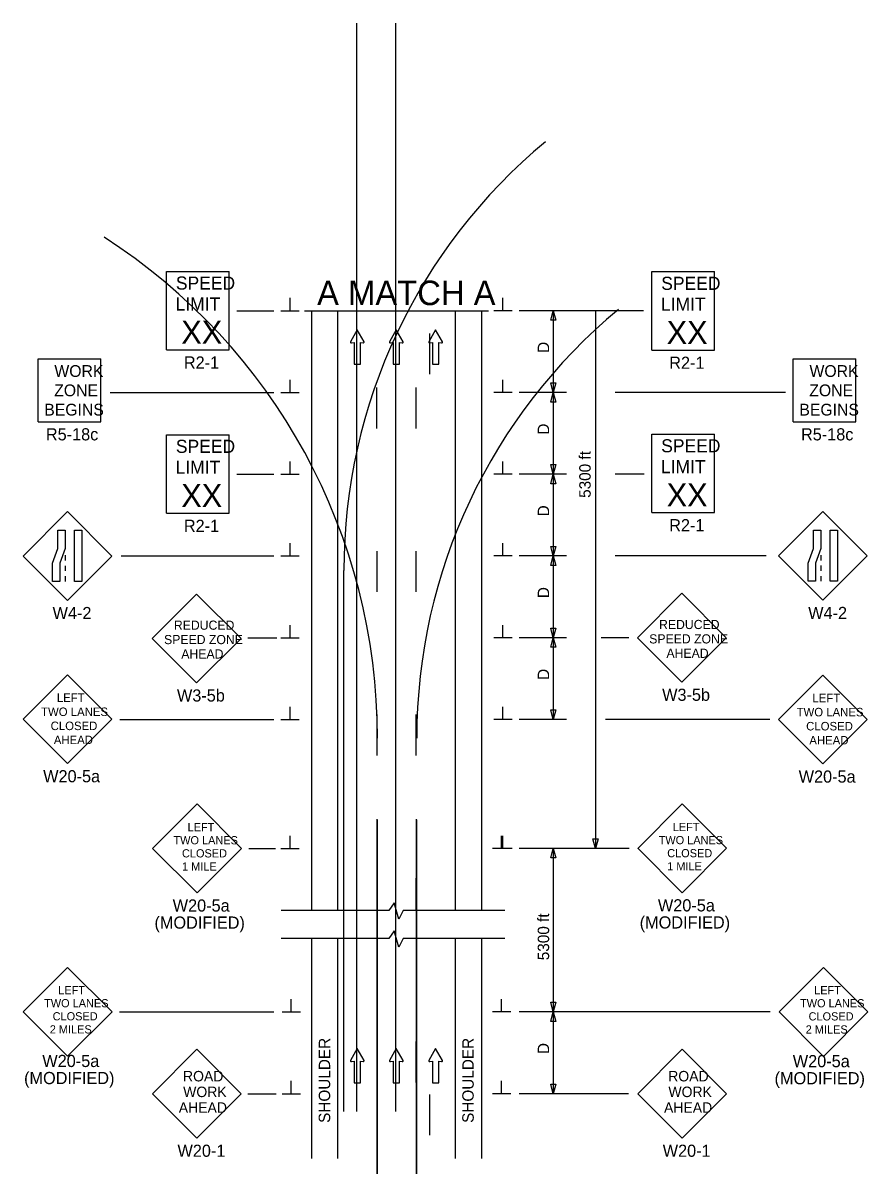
# Model space of a CAD drawing. Extents: x 16728 to 19508, y 5553 to 7079.
# Drawn here: x 17850 to 18368, y 6375 to 7079 of the extents above; entities that cross this region are included whole.
import ezdxf

# ---------------------------------------------------------------- set-up
doc = ezdxf.new("R2010")
doc.units = 0
for name, color, linetype in [('ALI_LEGAL_EX', 7, 'Continuous'), ('MT_SCRATCH_LEVEL_E', 7, 'Continuous'), ('PAVT_EDGE_EX', 7, 'Continuous'), ('TRAFFIC_SIGNS_PR', 7, 'Continuous'), ('TYPICAL_TEXT_DIMEN_PR', 7, 'Continuous')]:
    doc.layers.add(name, color=color, linetype=linetype)

msp = doc.modelspace()

# ---------------------------------------------------------------- linework, layer by layer
at = {"layer": 'ALI_LEGAL_EX'}
for p, q in [((18054.48, 7078.99), (18054.48, 6413.36)), ((18078.48, 7078.99), (18078.48, 6413.36)), ((18054.48, 6981.91), (18054.48, 6413.36)), ((18078.48, 6981.91), (18078.48, 6413.36)), ((18046.81, 6413.36), (18046.81, 6744.25)), ((18067.05, 6592.15), (18067.05, 6515)), ((18067.45, 6375.08), (18067.45, 6591.74)), ((18091.05, 6592.15), (18091.05, 6515)), ((18091.45, 6375.08), (18091.45, 6591.74)), ((18067.05, 6569), (18067.05, 6375.08)), ((18091.05, 6569), (18091.05, 6375.08))]:
    msp.add_line(p, q, dxfattribs=at)
for points in [[(18099.19, 6889.18), (18099.19, 6864.18)], [(18067.05, 6831.03), (18067.05, 6856.03)], [(18091.05, 6831.03), (18091.05, 6856.03)], [(18067.05, 6756.03), (18067.05, 6731.03)], [(18067.05, 6756.03), (18067.05, 6731.03)], [(18091.05, 6731.03), (18091.05, 6756.03)], [(18067.05, 6656.03), (18067.05, 6631.03)], [(18067.05, 6656.03), (18067.05, 6631.03)], [(18091.05, 6631.03), (18091.05, 6656.03)], [(18067.05, 6556.03), (18067.05, 6531.03)], [(18067.05, 6556.03), (18067.05, 6536.14)], [(18091.05, 6536.14), (18091.05, 6556.03)], [(18067.05, 6456.03), (18067.05, 6431.03)], [(18067.05, 6456.03), (18067.05, 6431.03)], [(18091.05, 6431.03), (18091.05, 6456.03)], [(18099.19, 6423.79), (18099.19, 6398.79)]]:
    msp.add_lwpolyline(points, dxfattribs=at)
for centre, radius, start, end in [((18386.81, 6744.25), 340, 129.56655, 180), ((17703.45, 6641.72), 364, 0, 57.29578), ((18431.45, 6641.72), 340, 129.56655, 180)]:
    msp.add_arc(centre, radius, start, end, dxfattribs=at)
at = {"layer": 'MT_SCRATCH_LEVEL_E'}
for p, q in [((18055.05, 6891.26), (18050.94, 6884.02)), ((18059.19, 6884.02), (18055.05, 6891.26)), ((18078.95, 6891.26), (18074.84, 6884.02)), ((18083.1, 6884.02), (18078.95, 6891.26)), ((18103, 6891.26), (18098.89, 6884.02)), ((18107.15, 6884.02), (18103, 6891.26)), ((18051.42, 6883.34), (18053.19, 6883.65)), ((18053.19, 6883.65), (18053.19, 6870.4)), ((18056.94, 6870.4), (18056.94, 6883.65)), ((18056.94, 6883.65), (18058.71, 6883.34)), ((18075.32, 6883.34), (18077.1, 6883.65)), ((18077.1, 6883.65), (18077.1, 6870.4)), ((18080.84, 6870.4), (18080.84, 6883.65)), ((18080.84, 6883.65), (18082.62, 6883.34)), ((18099.37, 6883.34), (18101.15, 6883.65)), ((18101.15, 6883.65), (18101.15, 6870.4)), ((18104.89, 6870.4), (18104.89, 6883.65)), ((18104.89, 6883.65), (18106.67, 6883.34)), ((18053.19, 6870.4), (18056.94, 6870.4)), ((18077.1, 6870.4), (18080.84, 6870.4)), ((18101.15, 6870.4), (18104.89, 6870.4)), ((18055.05, 6451.78), (18050.94, 6444.54)), ((18059.19, 6444.54), (18055.05, 6451.78)), ((18078.95, 6451.78), (18074.84, 6444.54)), ((18083.1, 6444.54), (18078.95, 6451.78)), ((18103, 6451.78), (18098.89, 6444.54)), ((18107.15, 6444.54), (18103, 6451.78)), ((18051.42, 6443.86), (18053.19, 6444.17)), ((18053.19, 6444.17), (18053.19, 6430.92)), ((18056.94, 6430.92), (18056.94, 6444.17)), ((18056.94, 6444.17), (18058.71, 6443.86)), ((18075.32, 6443.86), (18077.1, 6444.17)), ((18077.1, 6444.17), (18077.1, 6430.92)), ((18080.84, 6430.92), (18080.84, 6444.17)), ((18080.84, 6444.17), (18082.62, 6443.86)), ((18099.37, 6443.86), (18101.15, 6444.17)), ((18101.15, 6444.17), (18101.15, 6430.92)), ((18104.89, 6430.92), (18104.89, 6444.17)), ((18104.89, 6444.17), (18106.67, 6443.86)), ((18053.19, 6430.92), (18056.94, 6430.92)), ((18077.1, 6430.92), (18080.84, 6430.92)), ((18101.15, 6430.92), (18104.89, 6430.92))]:
    msp.add_line(p, q, dxfattribs=at)
for centre, start, end in [((18051.34, 6883.8), 150.42484, 279.96381), ((18058.78, 6883.8), 260.03619, 29.77312), ((18075.25, 6883.8), 150.42484, 279.96381), ((18082.69, 6883.8), 260.03619, 29.77312), ((18099.3, 6883.8), 150.42484, 279.96381), ((18106.74, 6883.8), 260.03619, 29.77312), ((18051.34, 6444.32), 150.42484, 279.96381), ((18058.78, 6444.32), 260.03619, 29.77312), ((18075.25, 6444.32), 150.42484, 279.96381), ((18082.69, 6444.32), 260.03619, 29.77312), ((18099.3, 6444.32), 150.42484, 279.96381), ((18106.74, 6444.32), 260.03619, 29.77312)]:
    msp.add_arc(centre, 0.463, start, end, dxfattribs=at)
at = {"layer": 'PAVT_EDGE_EX'}
for p, q in [((18027.05, 6903.04), (18027.05, 6536.14)), ((18043.05, 6903.04), (18043.05, 6536.14)), ((18115.05, 6903.04), (18115.05, 6536.14)), ((18131.05, 6903.04), (18131.05, 6536.14)), ((18027.05, 6519), (18027.05, 6384.62)), ((18043.05, 6519), (18043.05, 6384.62)), ((18115.05, 6519), (18115.05, 6384.62)), ((18131.05, 6519), (18131.05, 6384.62))]:
    msp.add_line(p, q, dxfattribs=at)
at = {"layer": 'TRAFFIC_SIGNS_PR'}
for p, q in [((17938.24, 6927.1), (17976.64, 6927.1)), ((17938.24, 6879.1), (17938.24, 6927.1)), ((17976.64, 6879.1), (17976.64, 6927.1)), ((18235.32, 6926.94), (18273.72, 6926.94)), ((18235.32, 6878.94), (18235.32, 6926.94)), ((18273.72, 6878.94), (18273.72, 6926.94)), ((17938.24, 6879.1), (17976.64, 6879.1)), ((18235.32, 6878.94), (18273.72, 6878.94)), ((17859.66, 6835.18), (17859.66, 6873.58)), ((17859.66, 6873.58), (17898.06, 6873.58)), ((17898.06, 6835.18), (17898.06, 6873.58)), ((18321.83, 6835.18), (18321.83, 6873.58)), ((18321.83, 6873.58), (18360.23, 6873.58)), ((18360.23, 6835.18), (18360.23, 6873.58)), ((17859.66, 6835.18), (17898.06, 6835.18)), ((18321.83, 6835.18), (18360.23, 6835.18)), ((17938.24, 6827.23), (17976.64, 6827.23)), ((17938.24, 6779.23), (17938.24, 6827.23)), ((17976.64, 6779.23), (17976.64, 6827.23)), ((18235.3, 6827.58), (18273.7, 6827.58)), ((18235.3, 6779.58), (18235.3, 6827.58)), ((18273.7, 6779.58), (18273.7, 6827.58)), ((17877.61, 6780.17), (17850.46, 6753.01)), ((17904.76, 6753.01), (17877.61, 6780.17)), ((17938.24, 6779.23), (17976.64, 6779.23)), ((18235.3, 6779.58), (18273.7, 6779.58)), ((18340.09, 6780.22), (18312.93, 6753.07)), ((18367.24, 6753.07), (18340.09, 6780.22)), ((17850.46, 6753.01), (17877.61, 6725.86)), ((17876.36, 6753.51), (17876.36, 6750.31)), ((17877.61, 6725.86), (17904.76, 6753.01)), ((18312.93, 6753.07), (18340.09, 6725.92)), ((18338.84, 6753.56), (18338.84, 6750.36)), ((18340.09, 6725.92), (18367.24, 6753.07)), ((17876.36, 6747.11), (17876.36, 6743.91)), ((18338.84, 6747.16), (18338.84, 6743.96)), ((17876.36, 6740.71), (17876.36, 6737.51)), ((18338.84, 6740.76), (18338.84, 6737.56)), ((17956.74, 6729.78), (17929.59, 6702.62)), ((17983.89, 6702.62), (17956.74, 6729.78)), ((18253.69, 6730.2), (18226.54, 6703.05)), ((18280.85, 6703.05), (18253.69, 6730.2)), ((17929.59, 6702.62), (17956.74, 6675.47)), ((17956.74, 6675.47), (17983.89, 6702.62)), ((18226.54, 6703.05), (18253.69, 6675.89)), ((18253.69, 6675.89), (18280.85, 6703.05)), ((17877.67, 6680.36), (17850.51, 6653.21)), ((17904.82, 6653.21), (17877.67, 6680.36)), ((18340.09, 6680.16), (18312.93, 6653)), ((18367.24, 6653), (18340.09, 6680.16)), ((17850.51, 6653.21), (17877.67, 6626.06)), ((17877.67, 6626.06), (17904.82, 6653.21)), ((18312.93, 6653), (18340.09, 6625.85)), ((18340.09, 6625.85), (18367.24, 6653)), ((17956.96, 6601.39), (17929.77, 6574.2)), ((17984.15, 6574.2), (17956.96, 6601.39)), ((18253.94, 6601.39), (18226.75, 6574.21)), ((18281.12, 6574.3), (18253.94, 6601.49)), ((17929.77, 6574.2), (17956.96, 6547.01)), ((17956.96, 6547.01), (17984.15, 6574.2)), ((18226.75, 6574.3), (18253.94, 6547.11)), ((18253.94, 6547.11), (18281.12, 6574.3)), ((17877.78, 6501.43), (17850.59, 6474.24)), ((17904.96, 6474.24), (17877.78, 6501.43)), ((18340.47, 6501.39), (18313.28, 6474.2)), ((18367.65, 6474.2), (18340.47, 6501.39)), ((17850.59, 6474.24), (17877.78, 6447.06)), ((17877.78, 6447.06), (17904.96, 6474.24)), ((18313.28, 6474.2), (18340.47, 6447.01)), ((18340.47, 6447.01), (18367.65, 6474.2)), ((17956.84, 6451.32), (17929.69, 6424.16)), ((17983.99, 6424.16), (17956.84, 6451.32)), ((18253.84, 6451.32), (18226.69, 6424.16)), ((18280.99, 6424.16), (18253.84, 6451.32)), ((17929.69, 6424.16), (17956.84, 6397.01)), ((17956.84, 6397.01), (17983.99, 6424.16)), ((18226.69, 6424.16), (18253.84, 6397.01)), ((18253.84, 6397.01), (18280.99, 6424.16))]:
    msp.add_line(p, q, dxfattribs=at)
for points in [[(17876.36, 6768.75), (17876.36, 6757.57), (17873.02, 6748.69), (17873.02, 6737.51), (17868.52, 6737.51), (17868.52, 6748.69), (17871.87, 6757.57), (17871.87, 6768.75)], [(17886.5, 6768.75), (17886.5, 6737.51), (17882, 6737.51), (17882, 6768.75)], [(18338.84, 6768.8), (18338.84, 6757.62), (18335.5, 6748.74), (18335.5, 6737.56), (18331, 6737.56), (18331, 6748.74), (18334.35, 6757.62), (18334.35, 6768.8)], [(18348.98, 6768.8), (18348.98, 6737.56), (18344.48, 6737.56), (18344.48, 6768.8)]]:
    msp.add_lwpolyline(points, close=True, dxfattribs=at)
at = {"layer": 'TYPICAL_TEXT_DIMEN_PR'}
for p, q in [((18013.92, 6903.04), (18013.92, 6910.83)), ((18144.17, 6903.04), (18144.17, 6910.83)), ((17981.38, 6903.04), (18004.05, 6903.04)), ((18008.3, 6903.04), (18019.55, 6903.04)), ((18022.72, 6903.04), (18135.37, 6903.04)), ((18149.8, 6903.04), (18138.55, 6903.04)), ((18230.27, 6903.04), (18154.05, 6903.04)), ((18173.48, 6897.18), (18175.05, 6903.04)), ((18175.05, 6903.04), (18175.05, 6853.04)), ((18175.05, 6903.04), (18176.62, 6897.18)), ((18200.89, 6903.04), (18200.89, 6574.2)), ((18175.05, 6897.18), (18173.48, 6897.18)), ((18176.62, 6897.18), (18175.05, 6897.18)), ((18013.92, 6853.04), (18013.92, 6860.83)), ((18144.17, 6853.04), (18144.17, 6860.83)), ((18175.05, 6853.04), (18173.48, 6858.91)), ((18173.48, 6858.91), (18175.05, 6858.91)), ((18175.05, 6858.91), (18176.62, 6858.91)), ((18176.62, 6858.91), (18175.05, 6853.04)), ((17903.73, 6853.04), (18004.05, 6853.04)), ((18008.3, 6853.04), (18019.55, 6853.04)), ((18149.8, 6853.04), (18138.55, 6853.04)), ((18183.05, 6853.04), (18154.05, 6853.04)), ((18173.48, 6847.18), (18175.05, 6853.04)), ((18175.05, 6853.04), (18175.05, 6803.04)), ((18175.05, 6853.04), (18176.62, 6847.18)), ((18317.09, 6853.04), (18212.91, 6853.04)), ((18175.05, 6847.18), (18173.48, 6847.18)), ((18176.62, 6847.18), (18175.05, 6847.18)), ((18013.92, 6803.04), (18013.92, 6810.83)), ((18144.17, 6803.04), (18144.17, 6810.83)), ((18175.05, 6803.04), (18173.48, 6808.91)), ((18173.48, 6808.91), (18175.05, 6808.91)), ((18175.05, 6808.91), (18176.62, 6808.91)), ((18176.62, 6808.91), (18175.05, 6803.04)), ((17981.38, 6803.04), (18004.05, 6803.04)), ((18008.3, 6803.04), (18019.55, 6803.04)), ((18149.8, 6803.04), (18138.55, 6803.04)), ((18183.05, 6803.04), (18154.05, 6803.04)), ((18173.48, 6797.18), (18175.05, 6803.04)), ((18175.05, 6803.04), (18175.05, 6753.04)), ((18175.05, 6803.04), (18176.62, 6797.18)), ((18230.75, 6803.04), (18212.91, 6803.04)), ((18175.05, 6797.18), (18173.48, 6797.18)), ((18176.62, 6797.18), (18175.05, 6797.18)), ((18013.92, 6753.04), (18013.92, 6760.83)), ((18144.17, 6753.04), (18144.17, 6760.83)), ((18175.05, 6753.04), (18173.48, 6758.91)), ((18173.48, 6758.91), (18175.05, 6758.91)), ((18175.05, 6758.91), (18176.62, 6758.91)), ((18176.62, 6758.91), (18175.05, 6753.04)), ((17910.58, 6753.04), (18004.05, 6753.04)), ((18008.3, 6753.04), (18019.55, 6753.04)), ((18149.8, 6753.04), (18138.55, 6753.04)), ((18183.05, 6753.04), (18154.05, 6753.04)), ((18173.48, 6747.18), (18175.05, 6753.04)), ((18175.05, 6753.04), (18175.05, 6703.04)), ((18175.05, 6753.04), (18176.62, 6747.18)), ((18305.38, 6753.04), (18212.91, 6753.04)), ((18175.05, 6747.18), (18173.48, 6747.18)), ((18176.62, 6747.18), (18175.05, 6747.18)), ((18013.92, 6703.04), (18013.92, 6710.83)), ((18144.17, 6703.04), (18144.17, 6710.83)), ((18175.05, 6703.04), (18173.48, 6708.91)), ((18173.48, 6708.91), (18175.05, 6708.91)), ((18175.05, 6708.91), (18176.62, 6708.91)), ((18176.62, 6708.91), (18175.05, 6703.04)), ((17988.12, 6703.04), (18005.83, 6703.04)), ((18008.3, 6703.04), (18019.55, 6703.04)), ((18149.8, 6703.04), (18138.55, 6703.04)), ((18183.05, 6703.04), (18154.05, 6703.04)), ((18173.48, 6697.18), (18175.05, 6703.04)), ((18175.05, 6703.04), (18175.05, 6653.04)), ((18175.05, 6703.04), (18176.62, 6697.18)), ((18221.32, 6703.04), (18204.38, 6703.04)), ((18175.05, 6697.18), (18173.48, 6697.18)), ((18176.62, 6697.18), (18175.05, 6697.18)), ((18013.92, 6653.04), (18013.92, 6660.83)), ((18144.17, 6653.04), (18144.17, 6660.83)), ((17909.79, 6653.04), (18004.05, 6653.04)), ((18008.3, 6653.04), (18019.55, 6653.04)), ((18149.8, 6653.04), (18138.55, 6653.04)), ((18183.05, 6653.04), (18154.05, 6653.04)), ((18175.05, 6653.04), (18173.48, 6658.91)), ((18173.48, 6658.91), (18175.05, 6658.91)), ((18175.05, 6658.91), (18176.62, 6658.91)), ((18176.62, 6658.91), (18175.05, 6653.04)), ((18307.54, 6653.04), (18206.97, 6653.04)), ((18013.92, 6574.2), (18013.92, 6581.98)), ((18143.42, 6574.2), (18143.42, 6581.98)), ((18144.17, 6574.2), (18144.17, 6581.98)), ((18200.89, 6574.2), (18199.32, 6580.06)), ((18199.32, 6580.06), (18200.89, 6580.06)), ((18200.89, 6580.06), (18202.46, 6580.06)), ((18202.46, 6580.06), (18200.89, 6574.2)), ((17988.75, 6574.2), (18005.04, 6574.2)), ((18008.3, 6574.2), (18019.55, 6574.2)), ((18149.05, 6574.2), (18137.8, 6574.2)), ((18149.8, 6574.2), (18138.55, 6574.2)), ((18221.46, 6574.2), (18154.05, 6574.2)), ((18173.48, 6568.34), (18175.05, 6574.2)), ((18175.05, 6568.34), (18173.48, 6568.34)), ((18175.05, 6574.2), (18175.05, 6474.2)), ((18175.05, 6574.2), (18176.62, 6568.34)), ((18176.62, 6568.34), (18175.05, 6568.34)), ((18077.65, 6540.94), (18074.4, 6536.14)), ((18080.39, 6531), (18077.65, 6540.94)), ((18074.4, 6536.14), (18008.45, 6536.14)), ((18083.14, 6536.14), (18080.39, 6531)), ((18145.47, 6536.14), (18083.14, 6536.14)), ((18074.4, 6519), (18008.45, 6519)), ((18077.65, 6523.8), (18074.4, 6519)), ((18080.39, 6513.86), (18077.65, 6523.8)), ((18083.14, 6519), (18080.39, 6513.86)), ((18145.47, 6519), (18083.14, 6519)), ((18014.67, 6474.2), (18014.67, 6481.98)), ((18143.42, 6474.2), (18143.42, 6481.98)), ((18175.05, 6474.2), (18173.48, 6480.06)), ((18173.48, 6480.06), (18175.05, 6480.06)), ((18175.05, 6480.06), (18176.62, 6480.06)), ((18176.62, 6480.06), (18175.05, 6474.2)), ((17909.49, 6474.2), (18004.05, 6474.2)), ((18009.05, 6474.2), (18020.3, 6474.2)), ((18149.05, 6474.2), (18137.8, 6474.2)), ((18307.79, 6474.2), (18154.05, 6474.2)), ((18173.48, 6468.34), (18175.05, 6474.2)), ((18175.05, 6474.2), (18175.05, 6424.2)), ((18175.05, 6474.2), (18176.62, 6468.34)), ((18175.05, 6468.34), (18173.48, 6468.34)), ((18176.62, 6468.34), (18175.05, 6468.34)), ((18014.67, 6424.2), (18014.67, 6431.98)), ((18143.42, 6424.2), (18143.42, 6431.98)), ((18175.05, 6424.2), (18173.48, 6430.06)), ((18173.48, 6430.06), (18175.05, 6430.06)), ((18175.05, 6430.06), (18176.62, 6430.06)), ((18176.62, 6430.06), (18175.05, 6424.2)), ((17988, 6424.2), (18005.31, 6424.2)), ((18009.05, 6424.2), (18020.3, 6424.2)), ((18149.05, 6424.2), (18137.8, 6424.2)), ((18221.16, 6424.2), (18154.05, 6424.2))]:
    msp.add_line(p, q, dxfattribs=at)

# ---------------------------------------------------------------- texts
at = {"layer": 'TRAFFIC_SIGNS_PR'}
for s, height, p in [('SPEED', 8, (17944.01, 6915.96)), ('SPEED', 8, (18241.09, 6915.8)), ('LIMIT', 8, (17943.84, 6903.16)), ('LIMIT', 8, (18240.93, 6903)), ('XX', 14.031, (17947.35, 6882.86)), ('XX', 14.031, (18244.43, 6882.7)), ('R2-1', 7.44, (17948.92, 6867.66)), ('R2-1', 7.44, (18246, 6867.5)), ('WORK', 7.217, (17869.66, 6862.54)), ('WORK', 7.217, (18331.84, 6862.54)), ('ZONE', 7.217, (17869.54, 6850.73)), ('ZONE', 7.217, (18331.72, 6850.73)), ('BEGINS', 7.217, (17863.47, 6838.93)), ('BEGINS', 7.217, (18325.65, 6838.93)), ('R5-18c', 7.44, (17864.47, 6823.74)), ('R5-18c', 7.44, (18326.65, 6823.74)), ('SPEED', 8, (17944.01, 6816.1)), ('SPEED', 8, (18241.07, 6816.44)), ('LIMIT', 8, (17943.84, 6803.3)), ('LIMIT', 8, (18240.9, 6803.65)), ('XX', 14.031, (17947.35, 6782.99)), ('XX', 14.031, (18244.41, 6783.34)), ('R2-1', 7.44, (17948.92, 6767.79)), ('R2-1', 7.44, (18245.98, 6768.14)), ('W4-2', 7.44, (17868.57, 6714.42)), ('W4-2', 7.44, (18331.04, 6714.48)), ('REDUCED', 5.6, (17942.8, 6707.93)), ('REDUCED', 5.6, (18239.75, 6708.35)), ('SPEED ZONE', 5.6, (17936.79, 6699.13)), ('SPEED ZONE', 5.6, (18233.74, 6699.55)), ('AHEAD', 5.6, (17947.35, 6690.33)), ('AHEAD', 5.6, (18244.3, 6690.75)), ('LEFT', 5.2, (17871.2, 6663.75)), ('W3-5b', 7.44, (17944.69, 6664.03)), ('W3-5b', 7.44, (18241.65, 6664.45)), ('LEFT', 5.2, (18333.63, 6663.55)), ('TWO LANES', 5.2, (17861.53, 6655.15)), ('TWO LANES', 5.2, (18323.95, 6654.95)), ('CLOSED', 5.2, (17867.38, 6646.55)), ('CLOSED', 5.2, (18329.8, 6646.35)), ('AHEAD', 5.2, (17869.32, 6637.95)), ('AHEAD', 5.2, (18331.75, 6637.75)), ('W20-5a', 7.44, (17862.81, 6614.62)), ('W20-5a', 7.44, (18325.23, 6614.42)), ('LEFT', 5.006, (17951.2, 6584.69)), ('LEFT', 5.006, (18248.18, 6584.79)), ('TWO LANES', 5.006, (17942.55, 6576.69)), ('TWO LANES', 5.006, (18239.53, 6576.79)), ('CLOSED', 5.006, (17947.78, 6568.68)), ('CLOSED', 5.006, (18244.76, 6568.78)), ('1 MILE', 5.006, (17947.78, 6560.67)), ('1 MILE', 5.006, (18244.76, 6560.77)), ('W20-5a', 7.449, (17942.08, 6535.56)), ('W20-5a', 7.449, (18239.06, 6535.66)), ('(MODIFIED)', 7.449, (17930.92, 6525.11)), ('(MODIFIED)', 7.449, (18227.9, 6525.21)), ('LEFT', 5.006, (17872.02, 6485.04)), ('LEFT', 5.006, (18334.71, 6484.99)), ('TWO LANES', 5.006, (17863.37, 6477.03)), ('TWO LANES', 5.006, (18326.06, 6476.99)), ('CLOSED', 5.006, (17868.6, 6469.02)), ('CLOSED', 5.006, (18331.29, 6468.98)), ('2 MILES', 5.006, (17866.85, 6461.02)), ('2 MILES', 5.006, (18329.54, 6460.97)), ('W20-5a', 7.449, (17862.27, 6440.49)), ('W20-5a', 7.449, (18321.62, 6440.37)), ('(MODIFIED)', 7.449, (17851.11, 6430.04)), ('ROAD', 6.4, (17948.38, 6431.7)), ('ROAD', 6.4, (18245.38, 6431.7)), ('(MODIFIED)', 7.449, (18310.46, 6429.92)), ('WORK', 6.4, (17948.49, 6422.1)), ('WORK', 6.4, (18245.49, 6422.1)), ('AHEAD', 6.4, (17945.8, 6412.5)), ('AHEAD', 6.4, (18242.8, 6412.5)), ('W20-1', 7.44, (17945.01, 6385.57)), ('W20-1', 7.44, (18242.01, 6385.57))]:
    msp.add_text(s, height=height, dxfattribs=at).set_placement(p)
at = {"layer": 'TYPICAL_TEXT_DIMEN_PR'}
msp.add_text('A MATCH A', height=15, dxfattribs=at).set_placement((18030.46, 6906.45))
for s, p in [('D', (18172.49, 6877.26)), ('D', (18172.49, 6827.26)), ('5300 ft', (18197.92, 6788.58)), ('D', (18172.49, 6777.26)), ('D', (18172.49, 6727.26)), ('D', (18172.49, 6677.26)), ('5300 ft', (18172.49, 6505.81)), ('SHOULDER', (18038.47, 6406.33)), ('SHOULDER', (18126.33, 6406.33)), ('D', (18172.49, 6448.42))]:
    msp.add_text(s, height=7, rotation=90, dxfattribs=at).set_placement(p)

doc.saveas('drawing.dxf')
